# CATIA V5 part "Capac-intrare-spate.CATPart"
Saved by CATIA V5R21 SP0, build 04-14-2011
Part number: Part1.1
Bounding box of the stored display mesh (mm): x -45.992 to 45.967, y 0 to 21.5, z -45.932 to 45.2
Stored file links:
  C:\Users\MIRCEA\Desktop\MOM\Mogan\model\Capac-intrare-spate.CATPart
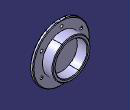
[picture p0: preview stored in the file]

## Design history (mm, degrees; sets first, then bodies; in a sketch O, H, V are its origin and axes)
Body1 (main body)
  Sketch1 on yz-plane, origin (0, 0, 0), H (0, 1, 0), V (0, 0, 1)
    line L1 (0, 0) -> (5, 0)
    line L2 (0, 0) -> (0, 46)
    line L3 (0, 46) -> (5, 46)
    line L4 (5, 46) -> (5, 31)
    line L5 (5, 31) -> (21.5, 31)
    line L6 (21.5, 31) -> (21.5, 26)
    line L7 (21.5, 26) -> (5, 26)
    point P7 (5, 26)
    line L8 (5, 26) -> (5, 0)
    length L1 = 5
    length L2 = 46
    length L4 = 15
    length L5 = 16.5
    length L6 = 5
    horizontal: L1 H, L3 H, L5 H, L7 H
    vertical: L2 V, L4 V, L6 V, L8 V
    coincidence: P7 L4
  Shaft1: profile Sketch1, axis Sketch1.L1, angle 360
  Sketch2 on face of Shaft1 from Sketch1.L2, origin (0, 0, 0), H (1, 0, 0), V (0, 0, 1)
    point P1 (0, 37.5)
    distance P1 O = 37.5
  Sketch3 on face of Shaft1 from Sketch1.L2, origin (0, 0, 47.5), H (1, 0, 0), V (0, 0, 1)
    point P1 (0, -10)
    reference projected point E1 (0, -10) from Sketch2.P1
    coincidence: E1 P1
  Hole1: placed by Sketch3, at (0, 0, 37.5) direction (0, 1, 0), diameter 5, through (limit type 6)
  CircPattern1: of Hole1, instances 6, angular step 60 {= 360.0*1 deg/CircPattern1.AngularNumber}, axis from face of Shaft1 from Sketch1.L2
  Sketch4 on zx-plane, origin (0, 0, 0), H (-1, 0, 0), V (0, 0, 1)
    point P1 (0, 45.2)
    line L1 (0, 45.2) -> (14.9451, 45.2)
    line L2 (0, 45.2) -> (-11.9737, 45.2)
    line L3 (-11.9737, 45.2) -> (-11.9737, 46.4989)
    line L4 (14.9451, 45.2) -> (14.9451, 46.4989)
    line L5 (14.9451, 46.4989) -> (-11.9737, 46.4989)
    distance O P1 = 45.2
    horizontal: L1 H, L2 H, L5 H
    vertical: L3 V, L4 V
  Pocket1: profile Sketch4, direction (0, 1, 0), length 20
  Chamfer1: length 1, angle 45, on edge [face of Shaft1 from Sketch1.L3 | face of Shaft1 from Sketch1.L4]; edge [face of Shaft1 from Sketch1.L2 | face of Shaft1 from Sketch1.L3]; edge [face of Shaft1 from Sketch1.L5 | face of Shaft1 from Sketch1.L6]; edge [face of Shaft1 from Sketch1.L6 | face of Shaft1 from Sketch1.L7]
